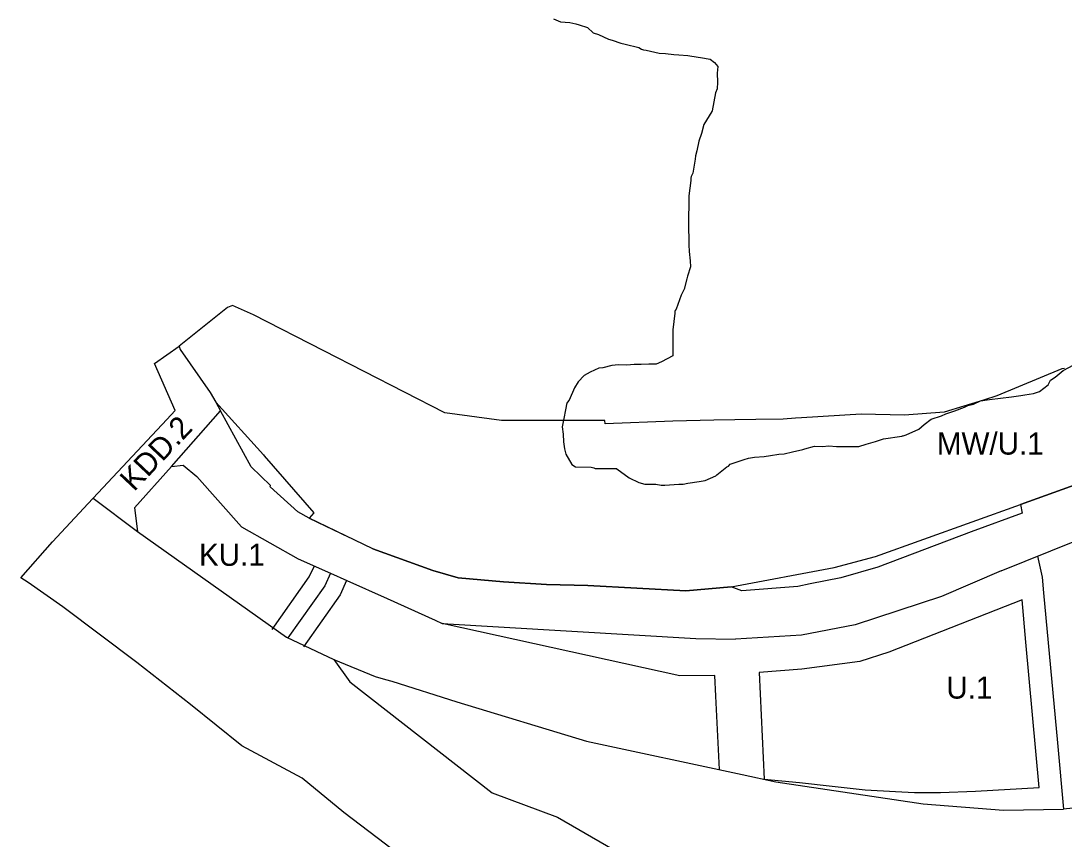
# Model space of a CAD drawing. Extents: x 7423571 to 7425893, y 5544590 to 5545833.
# Drawn here: x 7424211.2 to 7424447.1, y 5544859.3 to 5545044.4 of the extents above; entities that cross this region are included whole.
import ezdxf

# ---------------------------------------------------------------- set-up
doc = ezdxf.new("R2010")
doc.units = 0
for name, color, linetype in [('Default', 7, 'Continuous'), ('linie_rozgraniczające', 7, 'Continuous'), ('linie_zabudowy_nieprzekraczalne', 7, 'Continuous'), ('linie_zabudowy_obowiązujace', 7, 'Continuous'), ('oznaczenia_przeznaczen', 7, 'Continuous')]:
    doc.layers.add(name, color=color, linetype=linetype)

msp = doc.modelspace()

# ---------------------------------------------------------------- linework, layer by layer
at = {"layer": 'Default'}
msp.add_lwpolyline([(7424331.64, 5545044.8), (7424333.2, 5545044.13), (7424335.33, 5545044.03), (7424336.68, 5545043.71), (7424337.41, 5545043.49), (7424339.27, 5545042.84), (7424340.56, 5545041.68), (7424341.79, 5545041.3), (7424344.04, 5545040.24), (7424344.89, 5545040.02), (7424346.87, 5545039.34), (7424347.79, 5545039.1), (7424350.88, 5545038.31), (7424351.52, 5545037.93), (7424351.94, 5545037.82), (7424352.58, 5545037.74), (7424355.53, 5545037.06), (7424356.97, 5545036.95), (7424358.82, 5545036.79), (7424359.96, 5545036.65), (7424362, 5545036.5), (7424364.29, 5545036.14), (7424364.83, 5545036.06), (7424367.03, 5545035.72), (7424368, 5545034.94), (7424368.73, 5545034.03), (7424368.64, 5545032.55), (7424368.7, 5545030.48), (7424368.63, 5545029.02), (7424368.27, 5545028.09), (7424367.51, 5545024.05), (7424367.48, 5545024), (7424367.47, 5545023.97), (7424367.43, 5545023.88), (7424365.62, 5545020.91), (7424365.05, 5545018.87), (7424364.49, 5545017.14), (7424364.05, 5545015), (7424363.73, 5545013.81), (7424363.65, 5545013.11), (7424363.08, 5545009.91), (7424362.73, 5545009.15), (7424362.66, 5545008.77), (7424362.66, 5545008.28), (7424362.22, 5545004.81), (7424362.23, 5545003.75), (7424362.21, 5545002.58), (7424362.14, 5545000.08), (7424362.11, 5544998.74), (7424362.12, 5544997.27), (7424362.23, 5544995.18), (7424362.23, 5544993.74), (7424362.28, 5544992.23), (7424362.5, 5544990.12), (7424362.55, 5544988.75), (7424361.94, 5544986.64), (7424361.74, 5544986.01), (7424361.12, 5544983.68), (7424360.51, 5544982.34), (7424359.32, 5544979.16), (7424359.1, 5544978.83), (7424359.02, 5544978.6), (7424359.01, 5544978.25), (7424358.58, 5544974.5), (7424358.56, 5544973.57), (7424358.59, 5544972.57), (7424358.58, 5544969.7), (7424358.61, 5544968.57), (7424356.02, 5544967.24), (7424354.82, 5544966.73), (7424353.17, 5544966.7), (7424351.43, 5544966.67), (7424349.82, 5544966.65), (7424348.17, 5544966.49), (7424346.31, 5544966.58), (7424344.83, 5544966.42), (7424342.79, 5544965.87), (7424341.9, 5544965.83), (7424339.88, 5544964.9), (7424338.51, 5544964.16), (7424337.2, 5544962.7), (7424336.35, 5544961.34), (7424335.14, 5544958.54), (7424334.72, 5544958.03), (7424334.53, 5544957.59), (7424334.37, 5544956.74), (7424333.86, 5544954.02), (7424333.58, 5544952.54), (7424333.78, 5544950.89), (7424333.9, 5544949.17), (7424334.08, 5544947.56), (7424334.41, 5544946.35), (7424335.73, 5544944.05), (7424336.6, 5544943.51), (7424340.14, 5544943.42), (7424340.76, 5544943.25), (7424341.05, 5544943.12), (7424345.67, 5544943.12), (7424345.77, 5544943.1), (7424345.82, 5544943.08), (7424345.92, 5544943.04), (7424348.74, 5544941.03), (7424350.9, 5544939.96), (7424352.23, 5544939.61), (7424354.77, 5544939.54), (7424355.93, 5544939.35), (7424356.79, 5544939.33), (7424359.93, 5544939.6), (7424360.93, 5544939.59), (7424362.02, 5544939.79), (7424364.54, 5544940.15), (7424365.9, 5544940.41), (7424368.34, 5544941.46), (7424368.55, 5544941.65), (7424370.78, 5544943.48), (7424371.14, 5544943.68), (7424371.52, 5544944.08), (7424374.74, 5544945.18), (7424375.7, 5544945.45), (7424377.04, 5544945.65), (7424379.26, 5544945.82), (7424380.68, 5544946.05), (7424382.53, 5544946.39), (7424383.79, 5544946.45), (7424385.65, 5544946.9), (7424388, 5544947.38), (7424388.42, 5544947.56), (7424390.6, 5544948.17), (7424392.43, 5544948.1), (7424393.85, 5544948.24), (7424395.61, 5544948.12), (7424397.64, 5544948.11), (7424398.56, 5544948.12), (7424400.61, 5544948.11), (7424402.27, 5544948.65), (7424404.42, 5544949.26), (7424405.55, 5544949.62), (7424406.24, 5544949.79), (7424410.33, 5544950.46), (7424410.52, 5544950.5), (7424410.66, 5544950.53), (7424411.32, 5544950.7), (7424414.24, 5544952.04), (7424415.42, 5544953.1), (7424417.03, 5544954.27), (7424419.33, 5544955.01), (7424420.33, 5544955.47), (7424420.73, 5544955.67), (7424422.34, 5544956.15), (7424424.54, 5544956.97), (7424425.26, 5544957.33), (7424426.56, 5544957.64), (7424428.16, 5544958.43), (7424430.2, 5544958.72), (7424432.67, 5544959.05), (7424432.7, 5544959.06), (7424435.18, 5544959.29), (7424437.3, 5544959.62), (7424438.16, 5544959.78), (7424440.15, 5544960.11), (7424441.51, 5544960.56), (7424443.48, 5544962.01), (7424444.01, 5544963.06), (7424445.01, 5544963.8), (7424446.81, 5544965.29), (7424449.22, 5544966.56)], dxfattribs=at)
at = {"layer": 'linie_rozgraniczające'}
for p, q in [((7424245.28, 5544943.58), (7424256.35, 5544956.13)), ((7424227.54, 5544936.4), (7424237.59, 5544928.83)), ((7424236.89, 5544934.24), (7424237.59, 5544928.83)), ((7424237.59, 5544928.83), (7424271.26, 5544904.95)), ((7424271.26, 5544904.95), (7424281.98, 5544899.94))]:
    msp.add_line(p, q, dxfattribs=at)
for points in [[(7424447.12, 5544965.72), (7424446.5, 5544965.65), (7424431.86, 5544959.54), (7424428.8, 5544958.59), (7424419.9, 5544955.83), (7424410.94, 5544955.15), (7424401.16, 5544955.37), (7424387.65, 5544954.56), (7424386.32, 5544954.47), (7424383.5, 5544954.3), (7424377.38, 5544954.19), (7424367.89, 5544954.05), (7424358.58, 5544953.86), (7424343.26, 5544953.25), (7424343.23, 5544953.99), (7424319.84, 5544954.01), (7424307.02, 5544955.71), (7424279.71, 5544969.74), (7424263.82, 5544977.89), (7424259.07, 5544979.95), (7424257.94, 5544979.56), (7424247, 5544970.81)], [(7424226.41, 5544935.19), (7424244.18, 5544954.21), (7424246.07, 5544956.23), (7424241.38, 5544966.88), (7424247, 5544970.81)], [(7424247, 5544970.81), (7424247.19, 5544970.05), (7424253.99, 5544960.28), (7424255.24, 5544958.15), (7424256.35, 5544956.13)], [(7424454.11, 5544941.08), (7424437.17, 5544934.95), (7424437.54, 5544933.01), (7424426.03, 5544928.77), (7424404.96, 5544920.78), (7424396.54, 5544918.41), (7424389.63, 5544917.01), (7424386.86, 5544916.45), (7424374.16, 5544915.48), (7424371.81, 5544916.38), (7424361.54, 5544915.47), (7424339.39, 5544916.63), (7424330.01, 5544916.85), (7424320.3, 5544917.47), (7424310.08, 5544918.42), (7424304.37, 5544920.07), (7424290.75, 5544924.95), (7424276.39, 5544931.88), (7424273.78, 5544933.31), (7424267.54, 5544938.94), (7424267.61, 5544939.24), (7424263.29, 5544943.51), (7424256.35, 5544956.13)], [(7424432.84, 5544919.97), (7424477.32, 5544937.89), (7424482.11, 5544939.96), (7424509.39, 5544952.57)], [(7424245.28, 5544943.58), (7424236.89, 5544934.24)], [(7424245.28, 5544943.58), (7424247.87, 5544943.85), (7424250.99, 5544941.29), (7424261.08, 5544929.95), (7424273.91, 5544922.71), (7424281.22, 5544919.43)], [(7424587.52, 5544597.18), (7424574.78, 5544599.07), (7424519.85, 5544667.94), (7424486.37, 5544712.94), (7424449.24, 5544753.15), (7424428.54, 5544768.54), (7424402.59, 5544768.15), (7424400.64, 5544771.94), (7424390.09, 5544783.64), (7424385.55, 5544787.07), (7424337.05, 5544823.79), (7424333.3, 5544826.64), (7424328.79, 5544830.79), (7424293.66, 5544858.15), (7424284.18, 5544865.33), (7424274.79, 5544873.09), (7424261.19, 5544880.38), (7424249.55, 5544889.71), (7424237.44, 5544899.2), (7424220.67, 5544911.85), (7424212.85, 5544917.3), (7424211.2, 5544918.4), (7424218.32, 5544926.52), (7424226.41, 5544935.19)], [(7424441.05, 5544923.28), (7424442.07, 5544918.57), (7424442.4, 5544914.98), (7424445.52, 5544881.04), (7424446.88, 5544866.1)], [(7424432.84, 5544919.97), (7424419.36, 5544914.14), (7424399.83, 5544907.72), (7424387.67, 5544905.44), (7424372.73, 5544904.51)], [(7424281.22, 5544919.43), (7424279.89, 5544916.58), (7424271.58, 5544904.8)], [(7424281.22, 5544919.43), (7424284.86, 5544917.8), (7424294.02, 5544913.68), (7424304.83, 5544908.83)], [(7424598.16, 5544919.27), (7424580.47, 5544908.68), (7424561.86, 5544900.49), (7424536.44, 5544889.89), (7424525.12, 5544885.95), (7424510.47, 5544880.67), (7424486.42, 5544874.14), (7424483.47, 5544873.29), (7424467.38, 5544868.28), (7424465.8, 5544868.11), (7424446.88, 5544866.1)], [(7424304.83, 5544908.83), (7424306.47, 5544908.09), (7424363.81, 5544904.64), (7424372.73, 5544904.51)], [(7424281.98, 5544899.95), (7424285.58, 5544894.87), (7424317.74, 5544869.74), (7424332.55, 5544864.23), (7424378.27, 5544837.77)], [(7424281.98, 5544899.94), (7424291.33, 5544896.06), (7424293.62, 5544895.41), (7424295.06, 5544895), (7424309.77, 5544890.31), (7424339.1, 5544881.48), (7424374.27, 5544873.91), (7424381.89, 5544872.27), (7424415.16, 5544867.25), (7424433.35, 5544865.86), (7424446.88, 5544866.1)]]:
    msp.add_lwpolyline(points, dxfattribs=at)
at = {"layer": 'linie_zabudowy_nieprzekraczalne'}
for p, q in [((7424360.14, 5544896.21), (7424306.47, 5544908.09)), ((7424368.12, 5544896.27), (7424360.14, 5544896.21))]:
    msp.add_line(p, q, dxfattribs=at)
for points in [[(7424268.02, 5544906.69), (7424276.41, 5544918.59), (7424277.59, 5544921.12)], [(7424284.84, 5544917.75), (7424283.37, 5544914.57), (7424275.07, 5544902.81)], [(7424437.53, 5544913.39), (7424407.46, 5544901.61), (7424400.87, 5544899.43), (7424387.75, 5544897.7), (7424378.1, 5544896.96)], [(7424441.42, 5544871), (7424438.4, 5544903.81), (7424437.53, 5544913.39)], [(7424369.14, 5544875.01), (7424368.34, 5544891.62), (7424368.12, 5544896.27)], [(7424378.1, 5544896.96), (7424379.25, 5544872.84)], [(7424379.25, 5544872.84), (7424387.2, 5544872.06), (7424394.63, 5544871.26), (7424402.07, 5544870.46), (7424408.93, 5544870.03), (7424413.19, 5544869.86), (7424419.07, 5544869.84), (7424427.03, 5544870.16), (7424441.41, 5544871)]]:
    msp.add_lwpolyline(points, dxfattribs=at)
at = {"layer": 'linie_zabudowy_obowiązujace'}
for points in [[(7424437.17, 5544934.95), (7424454.11, 5544941.08), (7424462.84, 5544944.22), (7424473.11, 5544948.04), (7424487.52, 5544954.03), (7424501.03, 5544960.27), (7424507.57, 5544963.11), (7424514.73, 5544966.36), (7424528.37, 5544972.02), (7424544.86, 5544978.63)], [(7424247, 5544970.81), (7424247.19, 5544970.05), (7424253.99, 5544960.28), (7424255.24, 5544958.13), (7424266.04, 5544946.18), (7424266.24, 5544945.95), (7424277.44, 5544933.12), (7424276.39, 5544931.88), (7424285.37, 5544927.57)], [(7424371.81, 5544916.38), (7424395.04, 5544920.7), (7424404.42, 5544923.23), (7424437.17, 5544934.95)], [(7424290.75, 5544924.95), (7424304.37, 5544920.07), (7424310.08, 5544918.42), (7424320.3, 5544917.47), (7424330.01, 5544916.85), (7424339.39, 5544916.63), (7424361.54, 5544915.47), (7424371.81, 5544916.38)]]:
    msp.add_lwpolyline(points, dxfattribs=at)

# ---------------------------------------------------------------- texts
at = {"layer": 'oznaczenia_przeznaczen'}
msp.add_text('KDD.2', height=5, rotation=46.6138, dxfattribs=at).set_placement((7424236.78, 5544937.73))
for s, p in [('MW/U.1', (7424418.29, 5544946.26)), ('KU.1', (7424251.47, 5544921.11)), ('U.1', (7424420.43, 5544891.07))]:
    msp.add_text(s, height=5, dxfattribs=at).set_placement(p)

doc.saveas('drawing.dxf')
